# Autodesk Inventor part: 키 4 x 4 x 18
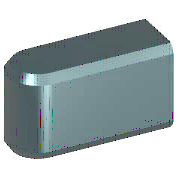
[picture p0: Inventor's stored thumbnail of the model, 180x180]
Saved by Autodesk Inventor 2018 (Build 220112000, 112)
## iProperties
IsCustomPart: 1
Created: 2012-02
Part Number: 키 4 x 4 x 18
Material: 강철, 연강
Description: 키 및 해당 키홈
Document SubType Name: Modeling
Standard: KS B 1311
Designer: mduedu
Standards Organization: KS
Language: ko-KR
Size Designation: 4 x 4 x 18
Categories: <MemberInstance><Categories><Category DisplayName="샤프트 부품" InternalName="7f7aeb1f-a693-4053-b835-cee3144e0d98" Mnemonic="SHFT"><Category DisplayName="키" Interna
Density: 1 g/cm^3
Appearance: 밝은 황색
Author: mduedu
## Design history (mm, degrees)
sketch "스케치1"
  geometry: L1 (2, 2)-(18, 2); L2 (18, 2)-(18, -2); L3 (18, -2)-(2, -2); L4 (0, 7)-(0, -7) reference; L5 (-5, 0)-(30, 0) reference; A1 r 2 centre (2, 0) between (2, 2) and (2, -2)
  constraints: 6 end point, 3 tangent, 2 point on circle, 1 centre point, 1 horizontal, 1 parallel, 1 perpendicular, 1 point on line
  dimensions: "d0" = 2 radius of A1 (= 0.5 x PB); "d7" = 18 distance between parallel lines of L2 L4 (= NLG)
workplane "Work Plane1"
workplane "Work Plane2"
extrude "본체1" new body sketch "스케치1" taper "d3" = 0 deg; stored distance "d4" = 10
workaxis "Work Axis1"
workplane "Work Plane4"
body "Solid1"
chamfer "모따기1" distance "d8" = 0.25 (= PHH); stored, may be unused: second distance "d9" = 0.25 (= PHH), angle "d13" = 45 deg
other parameters: "d1" = -2.5 (= -PNT), "d2" = 1.5 (= PH - PNT), "NLG" = 18 [user parameter; used in 2 equation terms], "PB" = 4 [user parameter; used in 1 equation term], "PNT" = 2.5 [user parameter; used in 2 equation terms], "PH" = 4 [user parameter; used in 1 equation term], "PHH" = 0.25 [user parameter; used in 2 equation terms], "d10" = 0, "d16" = 0, "d17" = 0, "d18" = 0, "RR" = 0.08 [user parameter], "WDMAX" = 12 [user parameter], "PLB1" = 18 (= NLG) [user parameter], "PUEB" = 1.8 [user parameter]
